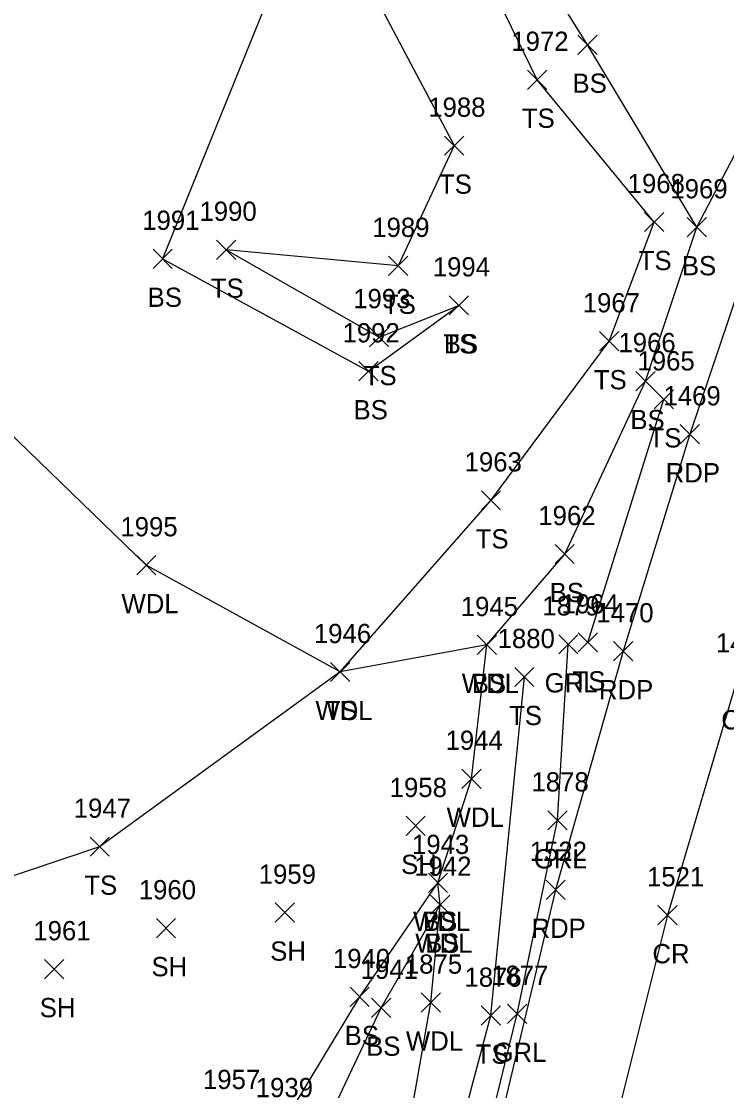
# Model space of a CAD drawing. Extents: x 1885914 to 1887218, y 756253 to 760620.
# Drawn here: x 1886387.4 to 1886460.8, y 759787.4 to 759898.5 of the extents above; entities that cross this region are included whole.
import ezdxf

# ---------------------------------------------------------------- set-up
doc = ezdxf.new("R2010")
doc.units = 0
for name, color, linetype in [('L_A', 7, 'Continuous'), ('L_I', 7, 'Continuous'), ('L_TIC', 7, 'Continuous'), ('LAWA', 7, 'Continuous'), ('LELB', 7, 'Continuous'), ('P_A', 7, 'Continuous'), ('P_I', 7, 'Continuous'), ('P_TIC', 7, 'Continuous'), ('PET', 7, 'Continuous'), ('PRC', 7, 'Continuous'), ('R_A', 7, 'Continuous'), ('R_I', 7, 'Continuous'), ('R_TIC', 7, 'Continuous'), ('RGR', 7, 'Continuous')]:
    doc.layers.add(name, color=color, linetype=linetype)

msp = doc.modelspace()

# ---------------------------------------------------------------- linework, layer by layer
at = {"layer": 'L_TIC'}
for points in [[(1886445.29, 759895.1), (1886447.29, 759897.1)], [(1886447.29, 759895.1), (1886445.29, 759897.1)], [(1886440.06, 759891.46), (1886442.06, 759893.46)], [(1886442.06, 759891.46), (1886440.06, 759893.46)], [(1886431.44, 759884.61), (1886433.44, 759886.61)], [(1886433.44, 759884.61), (1886431.44, 759886.61)], [(1886452.21, 759876.67), (1886454.21, 759878.67)], [(1886454.21, 759876.67), (1886452.21, 759878.67)], [(1886456.66, 759876.13), (1886458.66, 759878.13)], [(1886458.66, 759876.13), (1886456.66, 759878.13)], [(1886456.66, 759876.13), (1886458.66, 759878.13)], [(1886458.66, 759876.13), (1886456.66, 759878.13)], [(1886407.74, 759873.79), (1886409.74, 759875.79)], [(1886409.74, 759873.79), (1886407.74, 759875.79)], [(1886401.13, 759872.85), (1886403.13, 759874.85)], [(1886403.13, 759872.85), (1886401.13, 759874.85)], [(1886425.62, 759872.12), (1886427.62, 759874.12)], [(1886427.62, 759872.12), (1886425.62, 759874.12)], [(1886431.91, 759868.01), (1886433.91, 759870.01)], [(1886433.91, 759868.01), (1886431.91, 759870.01)], [(1886431.91, 759868.01), (1886433.91, 759870.01)], [(1886433.91, 759868.01), (1886431.91, 759870.01)], [(1886423.64, 759864.71), (1886425.64, 759866.71)], [(1886425.64, 759864.71), (1886423.64, 759866.71)], [(1886447.54, 759864.28), (1886449.54, 759866.28)], [(1886449.54, 759864.28), (1886447.54, 759866.28)], [(1886422.52, 759861.16), (1886424.52, 759863.16)], [(1886424.52, 759861.16), (1886422.52, 759863.16)], [(1886451.31, 759860.14), (1886453.31, 759862.14)], [(1886453.31, 759860.14), (1886451.31, 759862.14)], [(1886453.23, 759858.24), (1886455.23, 759860.24)], [(1886455.23, 759858.24), (1886453.23, 759860.24)], [(1886435.26, 759847.74), (1886437.26, 759849.74)], [(1886437.26, 759847.74), (1886435.26, 759849.74)], [(1886435.26, 759847.74), (1886437.26, 759849.74)], [(1886437.26, 759847.74), (1886435.26, 759849.74)], [(1886442.92, 759842.16), (1886444.92, 759844.16)], [(1886444.92, 759842.16), (1886442.92, 759844.16)], [(1886399.43, 759841), (1886401.43, 759843)], [(1886401.43, 759841), (1886399.43, 759843)], [(1886434.82, 759832.71), (1886436.82, 759834.71)], [(1886436.82, 759832.71), (1886434.82, 759834.71)], [(1886434.82, 759832.71), (1886436.82, 759834.71)], [(1886436.82, 759832.71), (1886434.82, 759834.71)], [(1886445.33, 759832.98), (1886447.33, 759834.98)], [(1886447.33, 759832.98), (1886445.33, 759834.98)], [(1886419.59, 759829.9), (1886421.59, 759831.9)], [(1886421.59, 759829.9), (1886419.59, 759831.9)], [(1886419.59, 759829.9), (1886421.59, 759831.9)], [(1886421.59, 759829.9), (1886419.59, 759831.9)], [(1886419.59, 759829.9), (1886421.59, 759831.9)], [(1886421.59, 759829.9), (1886419.59, 759831.9)], [(1886438.73, 759829.38), (1886440.73, 759831.38)], [(1886440.73, 759829.38), (1886438.73, 759831.38)], [(1886433.23, 759818.8), (1886435.23, 759820.8)], [(1886435.23, 759818.8), (1886433.23, 759820.8)], [(1886427.43, 759813.9), (1886429.43, 759815.9)], [(1886429.43, 759813.9), (1886427.43, 759815.9)], [(1886394.58, 759811.74), (1886396.58, 759813.74)], [(1886396.58, 759811.74), (1886394.58, 759813.74)], [(1886429.75, 759807.98), (1886431.75, 759809.98)], [(1886431.75, 759807.98), (1886429.75, 759809.98)], [(1886429.75, 759807.98), (1886431.75, 759809.98)], [(1886431.75, 759807.98), (1886429.75, 759809.98)], [(1886413.82, 759804.89), (1886415.82, 759806.89)], [(1886415.82, 759804.89), (1886413.82, 759806.89)], [(1886429.97, 759805.71), (1886431.97, 759807.71)], [(1886431.97, 759805.71), (1886429.97, 759807.71)], [(1886429.97, 759805.71), (1886431.97, 759807.71)], [(1886431.97, 759805.71), (1886429.97, 759807.71)], [(1886401.48, 759803.27), (1886403.48, 759805.27)], [(1886403.48, 759803.27), (1886401.48, 759805.27)], [(1886389.86, 759799.01), (1886391.86, 759801.01)], [(1886391.86, 759799.01), (1886389.86, 759801.01)], [(1886421.61, 759796.12), (1886423.61, 759798.12)], [(1886423.61, 759796.12), (1886421.61, 759798.12)], [(1886423.84, 759795), (1886425.84, 759797)], [(1886425.84, 759795), (1886423.84, 759797)], [(1886429, 759795.54), (1886431, 759797.54)], [(1886431, 759795.54), (1886429, 759797.54)], [(1886435.25, 759794.18), (1886437.25, 759796.18)], [(1886437.25, 759794.18), (1886435.25, 759796.18)]]:
    msp.add_lwpolyline(points, dxfattribs=at)
at = {"layer": 'LAWA'}
msp.add_lwpolyline([(1886420.25, 759558.57), (1886411.95, 759586.16), (1886411.02, 759591.73), (1886408.64, 759606.82), (1886405.28, 759619.96), (1886408.97, 759647.11), (1886409.34, 759668.38), (1886411.97, 759692.45), (1886411.89, 759715.23), (1886419.38, 759736.5), (1886421.95, 759756.23), (1886426.93, 759778.96), (1886430, 759796.54), (1886430.97, 759806.71), (1886430.75, 759808.98), (1886434.23, 759819.8), (1886435.82, 759833.71), (1886420.59, 759830.9), (1886400.43, 759842), (1886371.48, 759869.99)], dxfattribs=at)
at = {"layer": 'LELB'}
for points in [[(1886435.82, 759833.71), (1886443.92, 759843.16), (1886452.31, 759861.14), (1886457.66, 759877.13), (1886463.57, 759888.48), (1886474.59, 759918.53), (1886493.94, 759963.02), (1886508.21, 759990.58), (1886529.58, 760040.14)], [(1886318.4, 760004.48), (1886336.83, 759980.36), (1886361.56, 759955.89), (1886382.85, 759929.46), (1886414.19, 759903.62), (1886402.13, 759873.85), (1886423.52, 759862.16), (1886432.91, 759869.01)], [(1886330.28, 760003.4), (1886339.73, 759985.11), (1886367.35, 759962.72), (1886393.37, 759941.16), (1886421.61, 759906.02), (1886432.44, 759885.61), (1886426.62, 759873.12), (1886408.74, 759874.79), (1886424.64, 759865.71), (1886432.91, 759869.01)], [(1886436.26, 759848.74), (1886448.54, 759865.28), (1886453.21, 759877.67), (1886441.06, 759892.46), (1886428.32, 759918.66), (1886416.15, 759937.52)], [(1886457.66, 759877.13), (1886446.29, 759896.1), (1886430.81, 759920.94), (1886416.15, 759937.52)], [(1886446.33, 759833.98), (1886454.23, 759859.24)], [(1886420.59, 759830.9), (1886436.26, 759848.74)], [(1886420.59, 759830.9), (1886395.58, 759812.74), (1886365.13, 759802.51), (1886347.14, 759792.66), (1886310.58, 759769.85), (1886294.3, 759752.2)], [(1886482.43, 759330.53), (1886473.8, 759362.16), (1886466.41, 759391.35), (1886456.38, 759428.48), (1886448.84, 759459.02), (1886441.76, 759486.12), (1886435.76, 759515.56), (1886431.42, 759535.05), (1886426.06, 759559.46), (1886421.11, 759588.4), (1886418.79, 759606.26), (1886412.24, 759623.91), (1886411.78, 759647.7), (1886414.35, 759668.8), (1886416.75, 759691.58), (1886420.37, 759713.7), (1886423.9, 759735.67), (1886428.12, 759754.98), (1886431.72, 759778.14), (1886436.25, 759795.18), (1886439.73, 759830.38)], [(1886307, 759709.14), (1886318.52, 759725.02), (1886338.68, 759740.39), (1886365.24, 759749.52), (1886380.86, 759754.85), (1886394.35, 759762.41), (1886406.37, 759774.36), (1886414.51, 759783.7), (1886422.61, 759797.12), (1886430.75, 759808.98)], [(1886399.84, 759751.25), (1886408.63, 759764.61), (1886411.05, 759773.46), (1886418.12, 759781.79), (1886424.84, 759796), (1886430.97, 759806.71)]]:
    msp.add_lwpolyline(points, dxfattribs=at)
at = {"layer": 'P_TIC'}
for points in [[(1886455.93, 759854.61), (1886457.93, 759856.61)], [(1886457.93, 759854.61), (1886455.93, 759856.61)], [(1886448.99, 759832.06), (1886450.99, 759834.06)], [(1886450.99, 759832.06), (1886448.99, 759834.06)], [(1886441.98, 759807.26), (1886443.98, 759809.26)], [(1886443.98, 759807.26), (1886441.98, 759809.26)], [(1886453.6, 759804.62), (1886455.6, 759806.62)], [(1886455.6, 759804.62), (1886453.6, 759806.62)]]:
    msp.add_lwpolyline(points, dxfattribs=at)
at = {"layer": 'PET'}
msp.add_lwpolyline([(1886505.21, 759975.04), (1886485.32, 759931.76), (1886475.82, 759908.45), (1886466.13, 759882.96), (1886456.93, 759855.61), (1886449.99, 759833.06), (1886442.98, 759808.26), (1886435.87, 759778.49), (1886430.37, 759752.23), (1886424.92, 759721.57), (1886422.03, 759696.27), (1886420.3, 759670.71), (1886419.91, 759641.82), (1886421.23, 759616.47), (1886424.6, 759585.72), (1886430.09, 759554.32), (1886435.19, 759528.63), (1886443.72, 759490.84), (1886451.63, 759459.71), (1886459.13, 759429.12), (1886468.69, 759393.26), (1886479.71, 759351.07), (1886485.06, 759331.17)], dxfattribs=at)
at = {"layer": 'PRC'}
msp.add_lwpolyline([(1886516.05, 759969.43), (1886496.99, 759926.69), (1886487.66, 759904.2), (1886477.68, 759877.96), (1886468.59, 759851.92), (1886461.77, 759829.93), (1886454.6, 759805.62), (1886447.16, 759775.82), (1886441.74, 759748.8), (1886436.89, 759720.56), (1886434.02, 759695.25), (1886432.32, 759669.09), (1886432.26, 759642.82), (1886433.77, 759616.6), (1886436.98, 759587.84), (1886441.74, 759556.93), (1886446.53, 759531.43), (1886454.86, 759493.34), (1886462.57, 759461.76), (1886470.69, 759431.8), (1886480.02, 759395.82), (1886491.53, 759354.96), (1886496.99, 759335.08)], dxfattribs=at)
at = {"layer": 'R_TIC'}
for points in [[(1886443.3, 759832.77), (1886445.3, 759834.77)], [(1886445.3, 759832.77), (1886443.3, 759834.77)], [(1886442.17, 759814.48), (1886444.17, 759816.48)], [(1886444.17, 759814.48), (1886442.17, 759816.48)], [(1886437.97, 759794.37), (1886439.97, 759796.37)], [(1886439.97, 759794.37), (1886437.97, 759796.37)]]:
    msp.add_lwpolyline(points, dxfattribs=at)
at = {"layer": 'RGR'}
msp.add_lwpolyline([(1886414.69, 759633.21), (1886417.71, 759646.92), (1886419.44, 759668.57), (1886420.66, 759691.46), (1886423.11, 759713.75), (1886426.27, 759735.24), (1886429.87, 759755.44), (1886434.67, 759777.83), (1886438.97, 759795.37), (1886443.17, 759815.48), (1886444.3, 759833.77)], dxfattribs=at)

# ---------------------------------------------------------------- texts
at = {"layer": 'L_A'}
for s, p in [('BS', (1886444.73, 759891.1)), ('TS', (1886439.47, 759887.46)), ('TS', (1886430.85, 759880.61)), ('TS', (1886451.62, 759872.67)), ('BS', (1886456.1, 759872.13)), ('BS', (1886456.1, 759872.13)), ('TS', (1886407.14, 759869.79)), ('BS', (1886400.57, 759868.85)), ('TS', (1886425.03, 759868.12)), ('TS', (1886431.32, 759864.01)), ('BS', (1886431.35, 759864.01)), ('TS', (1886423.04, 759860.71)), ('TS', (1886446.95, 759860.28)), ('BS', (1886421.97, 759857.16)), ('BS', (1886450.75, 759856.14)), ('TS', (1886452.64, 759854.24)), ('TS', (1886434.67, 759843.74)), ('TS', (1886434.67, 759843.74)), ('BS', (1886442.36, 759838.16)), ('WDL', (1886397.85, 759837)), ('WDL', (1886433.23, 759828.71)), ('BS', (1886434.26, 759828.71)), ('TS', (1886444.74, 759828.98)), ('WDL', (1886418.01, 759825.9)), ('TS', (1886419, 759825.9)), ('TS', (1886419, 759825.9)), ('TS', (1886438.14, 759825.38)), ('WDL', (1886431.65, 759814.8)), ('SH', (1886426.92, 759809.9)), ('TS', (1886393.99, 759807.74)), ('WDL', (1886428.16, 759803.98)), ('BS', (1886429.19, 759803.98)), ('WDL', (1886428.39, 759801.71)), ('BS', (1886429.41, 759801.71)), ('SH', (1886413.31, 759800.89)), ('SH', (1886400.97, 759799.27)), ('SH', (1886389.35, 759795.01)), ('BS', (1886421.05, 759792.12)), ('WDL', (1886427.42, 759791.54)), ('BS', (1886423.28, 759791)), ('TS', (1886434.66, 759790.18))]:
    msp.add_text(s, height=2, dxfattribs=at).set_placement(p)
at = {"layer": 'L_I'}
for s, p in [('1972', (1886438.37, 759895.46)), ('1988', (1886429.74, 759888.61)), ('1968', (1886450.47, 759880.67)), ('1969', (1886454.91, 759880.13)), ('1969', (1886454.91, 759880.13)), ('1990', (1886405.96, 759877.79)), ('1991', (1886400.01, 759876.85)), ('1989', (1886423.92, 759876.12)), ('1994', (1886430.21, 759872.01)), ('1994', (1886430.21, 759872.01)), ('1993', (1886421.94, 759868.71)), ('1967', (1886445.8, 759868.28)), ('1992', (1886420.83, 759865.16)), ('1966', (1886449.51, 759864.14)), ('1965', (1886451.49, 759862.24)), ('1963', (1886433.52, 759851.74)), ('1963', (1886433.52, 759851.74)), ('1962', (1886441.18, 759846.16)), ('1995', (1886397.74, 759845)), ('1964', (1886443.59, 759836.98)), ('1945', (1886433.12, 759836.71)), ('1945', (1886433.12, 759836.71)), ('1946', (1886417.85, 759833.9)), ('1946', (1886417.85, 759833.9)), ('1946', (1886417.85, 759833.9)), ('1880', (1886436.95, 759833.38)), ('1944', (1886431.54, 759822.8)), ('1958', (1886425.73, 759817.9)), ('1947', (1886392.89, 759815.74)), ('1943', (1886428.05, 759811.98)), ('1943', (1886428.05, 759811.98)), ('1942', (1886428.28, 759809.71)), ('1942', (1886428.28, 759809.71)), ('1959', (1886412.12, 759808.89)), ('1960', (1886399.65, 759807.27)), ('1961', (1886388.69, 759803.01)), ('1940', (1886419.83, 759800.12)), ('1875', (1886427.31, 759799.54)), ('1941', (1886422.72, 759799)), ('1876', (1886433.5, 759798.18)), ('1957', (1886406.32, 759787.55)), ('1939', (1886411.81, 759786.7))]:
    msp.add_text(s, height=2, dxfattribs=at).set_placement(p)
at = {"layer": 'P_A'}
for s, p in [('RDP', (1886454.42, 759850.61)), ('RDP', (1886447.48, 759828.06)), ('CR', (1886460.2, 759824.93)), ('RDP', (1886440.47, 759803.26)), ('CR', (1886453.04, 759800.62))]:
    msp.add_text(s, height=2, dxfattribs=at).set_placement(p)
at = {"layer": 'P_I'}
for s, p in [('1469', (1886454.19, 759858.61)), ('1470', (1886447.21, 759836.06)), ('1471', (1886459.64, 759832.93)), ('1522', (1886440.29, 759811.26)), ('1521', (1886452.48, 759808.62))]:
    msp.add_text(s, height=2, dxfattribs=at).set_placement(p)
at = {"layer": 'R_A'}
for p in [(1886441.84, 759828.77), (1886440.71, 759810.48), (1886436.52, 759790.37)]:
    msp.add_text('GRL', height=2, dxfattribs=at).set_placement(p)
at = {"layer": 'R_I'}
for s, p in [('1879', (1886441.6, 759836.77)), ('1878', (1886440.47, 759818.48)), ('1877', (1886436.28, 759798.37))]:
    msp.add_text(s, height=2, dxfattribs=at).set_placement(p)

doc.saveas('drawing.dxf')
